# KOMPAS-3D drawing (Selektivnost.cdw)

Views: Вид 1
Referenced files: селективность.cdw
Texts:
  КП 13.02.11 ЭО-20 2023
  Карта селективности ступеней МТЗ
  User
  Noncommercial version
  Iн.д.=55,4А
  Iн.ШРА=249А
  Iпуск.дв.=415,5А
  ВА55-41 1000 1000
  ВА51-35 250 250
  ВА51-31 100 63
  ВВГнг(3х10+1 6)мм 2
  ВВГ(3 95)мм 2
  ШРА4-250
  ШМА4-1250
  ТСЗА 630 10
  rтр
  хтр
  rшма
  хшма
  rВВГ2
  хВВГ2
  rшра
  хшра
  rВВГнг1
  хВВГнг1
  КЗ-1
  КЗ-2
  КЗ-3
  Пресс №14
  Рн=30кВт
  Uн380В
  сек.
  мин.
  Iн.расц.магн. у ВА51-31 100 63 =1000А
  Iн.расц.магн. у ВА51-35 250 250 =1500А
  Iн.расц.магн. у ВА55-41 1000 1000 =5000А
  Карта селективности
  ступеней МТЗ
  ВКР 13.02.11 ЭО-18 2022г-
Dimensions and other numbers on the sheet: 0,005; 0,01; 0,02; 0,05; 0,1; 0,2; 0,5; 1; 2; 5; 10; 20; 50; 100; 200; 500; 1000; 2000; 5000; 10000; 20000; 30000; 50000; 100000; 10кВ; 0,0031; 0,0136; 0,000085; 0,000013; 0,000195; 0,000081; 0,00042; 0,00184; 0,000099; 0; 3; 4; 6; 7; 8; 9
